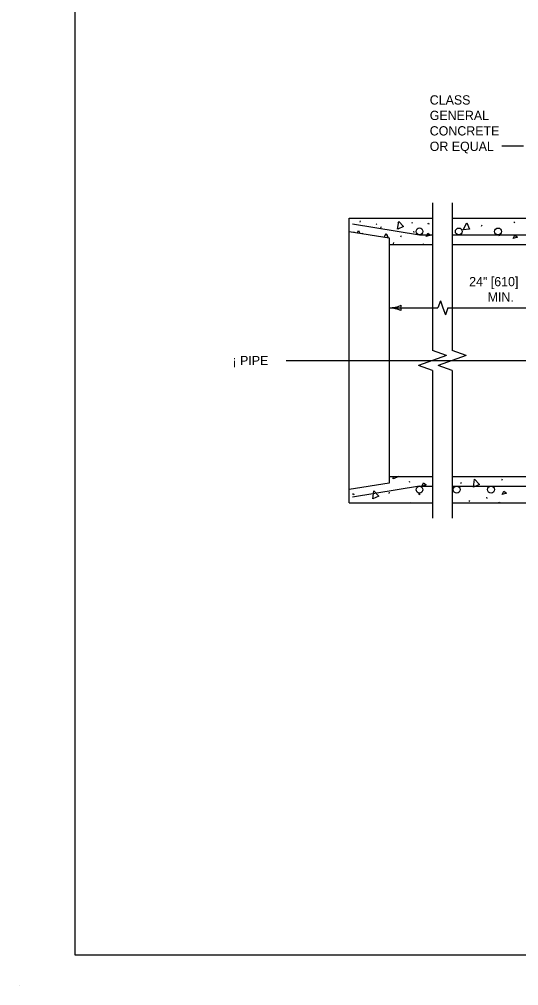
# Model space of a CAD drawing. Extents: x 49991.4 to 50021, y 49987.6 to 50011.4.
# Drawn here: x 49999.98 to 50003.21, y 49999.86 to 50006.11 of the extents above; entities that cross this region are included whole.
import ezdxf

# ---------------------------------------------------------------- set-up
doc = ezdxf.new("R2010")
doc.units = 0
for name, color, linetype in [('Level 1', 7, 'Continuous'), ('Level 2', 7, 'Continuous'), ('Level 3', 7, 'Continuous'), ('Level 5', 7, 'Continuous'), ('Level 6', 7, 'Continuous')]:
    doc.layers.add(name, color=color, linetype=linetype)

msp = doc.modelspace()

# ---------------------------------------------------------------- linework, layer by layer
at = {"layer": 'Level 1'}
for p, q in [((50002.1091, 50002.985), (50002.1091, 50004.8236)), ((50002.1091, 50004.8236), (50002.6491, 50004.8236)), ((50002.1805, 50004.7985), (50002.1841, 50004.8065)), ((50002.7761, 50004.8236), (50004.0705, 50004.8236)), ((50002.1325, 50004.7871), (50002.5648, 50004.7168)), ((50002.2857, 50004.7886), (50002.2893, 50004.7832)), ((50002.3155, 50004.7621), (50002.3191, 50004.7701)), ((50002.4273, 50004.7953), (50002.4308, 50004.8033)), ((50002.5166, 50004.7916), (50002.5201, 50004.7996)), ((50002.6182, 50004.7943), (50002.6218, 50004.789)), ((50002.6228, 50004.7923), (50002.6263, 50004.7869)), ((50002.9665, 50004.7733), (50002.9701, 50004.7813)), ((50003.177, 50004.7938), (50003.1805, 50004.8018)), ((50002.1091, 50004.7389), (50002.3692, 50004.6966)), ((50002.1417, 50004.7336), (50002.143, 50004.7365)), ((50002.3554, 50004.7081), (50002.3589, 50004.716)), ((50002.3692, 50004.6966), (50002.3692, 50003.1119)), ((50002.4447, 50004.7043), (50002.4482, 50004.7123)), ((50002.5266, 50004.7398), (50002.5275, 50004.7318)), ((50002.5648, 50004.7168), (50002.6491, 50004.7168)), ((50002.7761, 50004.7168), (50004.0941, 50004.7168)), ((50003.0775, 50004.7165), (50003.0811, 50004.7112)), ((50002.3692, 50004.6543), (50002.6491, 50004.6543)), ((50002.3963, 50004.6591), (50002.3999, 50004.6671)), ((50002.5872, 50004.6581), (50002.5898, 50004.6543)), ((50002.5918, 50004.6561), (50002.593, 50004.6543)), ((50002.7761, 50004.6543), (50004.1091, 50004.6543)), ((50002.3692, 50003.1543), (50002.6491, 50003.1543)), ((50002.4983, 50003.1252), (50002.4992, 50003.1172)), ((50002.7761, 50003.1543), (50004.3994, 50003.1543)), ((50003.0973, 50003.1312), (50003.1009, 50003.1392)), ((50002.3692, 50003.1119), (50002.1091, 50003.0697)), ((50002.5648, 50003.0917), (50002.1325, 50003.0214)), ((50002.5648, 50003.0917), (50002.6491, 50003.0917)), ((50002.7761, 50003.0917), (50004.416, 50003.0917)), ((50002.8332, 50003.1093), (50002.8368, 50003.1173)), ((50002.1325, 50003.0435), (50002.1361, 50003.0382)), ((50002.1371, 50003.0415), (50002.1407, 50003.0361)), ((50002.368, 50003.0445), (50002.3715, 50003.0525)), ((50002.5589, 50003.0435), (50002.5625, 50003.0382)), ((50002.5635, 50003.0415), (50002.567, 50003.0361)), ((50002.8867, 50002.9918), (50002.8903, 50002.9998)), ((50002.9989, 50003.0198), (50002.9998, 50003.0118)), ((50002.1091, 50002.985), (50002.6491, 50002.985)), ((50002.5097, 50002.9848), (50002.5101, 50002.9857)), ((50002.7761, 50002.985), (50004.4328, 50002.985)), ((50003.0777, 50002.9908), (50003.0812, 50002.9855)), ((50003.0822, 50002.9888), (50003.0847, 50002.985)), ((49999.9766, 49999.8624), (49999.9766, 49999.8624))]:
    msp.add_line(p, q, dxfattribs=at)
msp.add_lwpolyline([(50008.6146, 50011.2628), (50000.3356, 50011.2628), (50000.3356, 50000.0624), (50008.6146, 50000.0624)], close=True, dxfattribs=at)
for points in [[(50002.1629, 50004.7319), (50002.1702, 50004.7457), (50002.1774, 50004.7296)], [(50002.4235, 50004.7529), (50002.4306, 50004.8037), (50002.4624, 50004.7708), (50002.4244, 50004.7532)], [(50002.8466, 50004.7494), (50002.8706, 50004.7947), (50002.8893, 50004.7529), (50002.8475, 50004.7494)], [(50002.192, 50004.7254), (50002.193, 50004.7275), (50002.1968, 50004.7246)], [(50002.3362, 50004.702), (50002.3488, 50004.7257), (50002.3612, 50004.6979)], [(50002.6087, 50004.7053), (50002.6193, 50004.7275), (50002.6371, 50004.7142), (50002.6087, 50004.7053)], [(50003.1708, 50004.6934), (50003.1814, 50004.7156), (50003.1992, 50004.7023), (50003.1708, 50004.6934)], [(50002.3952, 50003.1383), (50002.3974, 50003.1543)], [(50002.43, 50003.1543), (50002.396, 50003.1386)], [(50002.914, 50003.0856), (50002.921, 50003.1364), (50002.9528, 50003.1035), (50002.9148, 50003.0859)], [(50002.2631, 50003.0103), (50002.2702, 50003.0611), (50002.302, 50003.0282), (50002.264, 50003.0106)], [(50002.5804, 50003.0907), (50002.591, 50003.1129), (50002.6088, 50003.0996), (50002.5804, 50003.0907)], [(50003.0991, 50003.038), (50003.1098, 50003.0602), (50003.1275, 50003.0469), (50003.0991, 50003.038)]]:
    msp.add_lwpolyline(points, dxfattribs=at)
for centre in [(50002.5649, 50004.7392), (50002.8189, 50004.7389), (50003.073, 50004.7389), (50002.5648, 50003.0693), (50002.8054, 50003.0696), (50003.0276, 50003.0696)]:
    msp.add_circle(centre, 0.0221, dxfattribs=at)
at = {"layer": 'Level 3'}
for p, q in [((50003.2384, 50005.2892), (50003.0974, 50005.2892)), ((50002.3692, 50004.2444), (50002.684, 50004.2444)), ((50002.7002, 50004.2901), (50002.684, 50004.2444)), ((50002.7002, 50004.2901), (50002.7164, 50004.2444)), ((50002.7164, 50004.2444), (50002.7326, 50004.1987)), ((50002.7488, 50004.2444), (50002.7326, 50004.1987)), ((50002.7488, 50004.2444), (50003.9815, 50004.2444))]:
    msp.add_line(p, q, dxfattribs=at)
for centre, radius, start, end in [((50002.3577, 50004.4771), 0.233, 272.82731, 292.07716), ((50002.36, 50004.0223), 0.2223, 67.45601, 87.63952), ((50002.4974, 50004.2444), 0.0548, 162.13882, 197.86118)]:
    msp.add_arc(centre, radius, start, end, dxfattribs=at)
at = {"layer": 'Level 5'}
msp.add_lwpolyline([(50001.7017, 50003.9043), (50005.0419, 50003.9043)], dxfattribs=at)
at = {"layer": 'Level 6'}
for p, q in [((50002.6491, 50004.9236), (50002.6491, 50003.9691)), ((50002.7761, 50004.9236), (50002.7761, 50003.9691)), ((50002.7405, 50003.9367), (50002.6491, 50003.9691)), ((50002.7405, 50003.9367), (50002.6491, 50003.9043)), ((50002.8675, 50003.9367), (50002.7761, 50003.9691)), ((50002.8675, 50003.9367), (50002.7761, 50003.9043)), ((50002.6491, 50003.9043), (50002.5577, 50003.8719)), ((50002.6491, 50003.8395), (50002.5577, 50003.8719)), ((50002.7761, 50003.9043), (50002.6847, 50003.8719)), ((50002.7761, 50003.8395), (50002.6847, 50003.8719)), ((50002.6491, 50003.8395), (50002.6491, 50002.885)), ((50002.7761, 50003.8395), (50002.7761, 50002.885))]:
    msp.add_line(p, q, dxfattribs=at)

# ---------------------------------------------------------------- texts
at = {"layer": 'Level 2'}
for s, p in [('CLASS', (50002.6312, 50005.5592)), ('GENERAL', (50002.6312, 50005.4592)), ('CONCRETE', (50002.6312, 50005.3592)), ('OR EQUAL', (50002.6312, 50005.2592)), ('24" [610] ', (50002.8862, 50004.3844)), ('MIN.', (50003.0058, 50004.2844)), ('¡ PIPE', (50001.3551, 50003.8743))]:
    msp.add_text(s, height=0.06, dxfattribs=at).set_placement(p)

doc.saveas('drawing.dxf')
